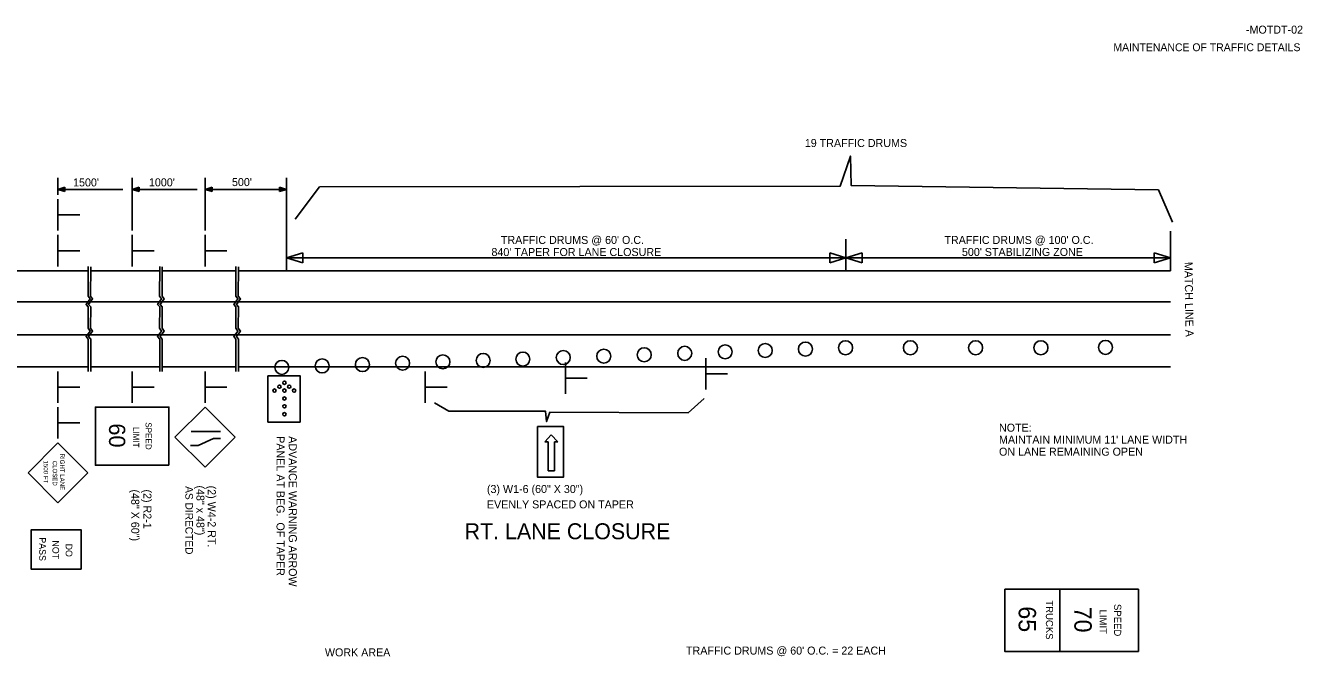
# Model space of a CAD drawing. Extents: x 37171 to 39457, y -18939 to -17445.
# Drawn here: x 38020 to 39456, y -18154 to -17445 of the extents above; entities that cross this region are included whole.
import ezdxf

# ---------------------------------------------------------------- set-up
doc = ezdxf.new("R2010")
doc.units = 0
for name, color, linetype in [('Default', 7, 'Continuous'), ('R_Const Phase 4', 7, 'Continuous'), ('R_Grid Annot', 7, 'Continuous'), ('R_Proposed Road Annot', 7, 'Continuous')]:
    doc.layers.add(name, color=color, linetype=linetype)

msp = doc.modelspace()

# ---------------------------------------------------------------- linework, layer by layer
at = {"layer": 'Default'}
for p, q in [((38221.4, -17873.7), (38187.6, -17907.5)), ((38221.4, -17873.7), (38255.1, -17907.5)), ((38205.7, -17901), (38238.9, -17901)), ((38603.6, -17912.6), (38610.8, -17904.7)), ((38610.8, -17904.7), (38618.1, -17912.6)), ((38022.3, -17947.7), (38055.9, -17914)), ((38089.6, -17947.6), (38055.9, -17914)), ((38187.6, -17907.5), (38221.4, -17941.2)), ((38205, -17916.7), (38213.6, -17916.7)), ((38213.6, -17916.7), (38230.8, -17908.8)), ((38255.1, -17907.5), (38221.4, -17941.2)), ((38230.8, -17908.8), (38238.9, -17908.8)), ((38607.2, -17912.6), (38603.6, -17912.6)), ((38607.2, -17945.3), (38607.2, -17912.6)), ((38614.5, -17945.3), (38614.5, -17912.6)), ((38614.5, -17912.6), (38618.1, -17912.6)), ((38056, -17981.4), (38022.3, -17947.7)), ((38056, -17981.4), (38089.6, -17947.6)), ((38607.2, -17945.3), (38614.5, -17945.3))]:
    msp.add_line(p, q, dxfattribs=at)
for points in [[(38292.1, -17838.5), (38292.1, -17890.6), (38328.2, -17890.6), (38328.2, -17838.5)], [(38180.7, -17939.1), (38098.2, -17939.1), (38098.2, -17873.7), (38180.7, -17873.7)], [(38595.3, -17895.4), (38595.3, -17952.6), (38624.5, -17952.6), (38624.5, -17895.4)], [(38081.9, -18056), (38025.9, -18056), (38025.9, -18011.6), (38081.9, -18011.6)], [(39182.7, -18148.6), (39121, -18148.6), (39121, -18078.6), (39182.7, -18078.6)], [(39271, -18148.6), (39182.7, -18148.6), (39182.7, -18078.6), (39271, -18078.6)]]:
    msp.add_lwpolyline(points, close=True, dxfattribs=at)
for centre, radius in [((38760.8, -17813.2), 7.88), ((38806.3, -17811.5), 7.88), ((38851.4, -17810), 7.88), ((38896.6, -17808.4), 7.88), ((38941.7, -17806.9), 7.88), ((39014.6, -17806.9), 7.88), ((39088, -17806.9), 7.88), ((39161.4, -17806.9), 7.88), ((39234, -17806.5), 7.88), ((38353.1, -17827.4), 7.88), ((38398.4, -17825.9), 7.88), ((38443.6, -17824.3), 7.88), ((38488.9, -17822.8), 7.88), ((38534.2, -17821.2), 7.88), ((38578.8, -17819.7), 7.88), ((38624.3, -17818), 7.88), ((38669.8, -17816.4), 7.88), ((38715.3, -17814.8), 7.88), ((38307.8, -17829), 7.88), ((38305.1, -17850.7), 1.84), ((38310.6, -17846.3), 1.84), ((38316.1, -17850.7), 1.84), ((38299.5, -17855.1), 1.84), ((38310.6, -17855.1), 1.84), ((38310.6, -17864), 1.84), ((38321.6, -17855.1), 1.84), ((38310.6, -17872.8), 1.84), ((38310.6, -17881.7), 1.84)]:
    msp.add_circle(centre, radius, dxfattribs=at)
at = {"layer": 'R_Const Phase 4'}
for p, q in [((38055.9, -17675.1), (38055.9, -17639.8)), ((38056.4, -17657.5), (38080.5, -17657.5)), ((38055.9, -17715.4), (38055.9, -17680.1)), ((38139.5, -17715.4), (38139.5, -17680.1)), ((38221.4, -17715.4), (38221.4, -17680.1)), ((38056.4, -17697.8), (38080.5, -17697.8)), ((38140, -17697.8), (38164, -17697.8)), ((38221.9, -17697.8), (38246, -17697.8)), ((38002.2, -17720.4), (38090, -17720.4)), ((38092.8, -17720.4), (38170.4, -17720.4)), ((38173.2, -17720.4), (38256.2, -17720.4)), ((38259, -17720.4), (38313, -17720.4)), ((38313, -17720.4), (39307.2, -17720.4)), ((37171.8, -17755.3), (39307.2, -17755.3)), ((37171.8, -17792.5), (39307.2, -17792.5)), ((38784.5, -17853.7), (38784.5, -17818.5)), ((38002.4, -17828.5), (38090.2, -17828.5)), ((38055.9, -17868.7), (38055.9, -17833.5)), ((38093, -17828.5), (38170.7, -17828.5)), ((38139.5, -17868.7), (38139.5, -17833.5)), ((38173.5, -17828.5), (38256.4, -17828.5)), ((38221.4, -17868.7), (38221.4, -17833.5)), ((38259.2, -17828.5), (38313, -17828.5)), ((38313, -17828.5), (39307.2, -17828.5)), ((38468.9, -17868.7), (38468.9, -17833.5)), ((38626.7, -17858.7), (38626.7, -17823.5)), ((38627.2, -17841.2), (38651.3, -17841.2)), ((38785, -17836.2), (38809.1, -17836.2)), ((38056.4, -17851.2), (38080.5, -17851.2)), ((38140, -17851.2), (38164, -17851.2)), ((38221.9, -17851.2), (38246, -17851.2)), ((38469.5, -17851.2), (38493.5, -17851.2)), ((38055.9, -17909), (38055.9, -17873.7)), ((38056.4, -17891.4), (38080.5, -17891.4))]:
    msp.add_line(p, q, dxfattribs=at)
for points in [[(38322.6, -17662.4), (38350.2, -17625.8), (38935.8, -17625.1), (38947.1, -17591.3), (38948.1, -17624.6), (39293.5, -17629.3), (39309.4, -17665.7)], [(38090, -17715.6), (38089.8, -17748.8), (38092.1, -17752.1), (38087.6, -17758.2), (38090, -17761)], [(38092.8, -17715.8), (38092.6, -17748.8), (38094.9, -17752.1), (38090.4, -17758.2), (38092.8, -17761)], [(38170.4, -17715.6), (38170.2, -17748.8), (38172.5, -17752.1), (38168.1, -17758.2), (38170.4, -17761)], [(38173.2, -17715.8), (38173, -17748.8), (38175.3, -17752.1), (38170.9, -17758.2), (38173.2, -17761)], [(38256.2, -17715.6), (38256, -17748.8), (38258.3, -17752.1), (38253.8, -17758.2), (38256.2, -17761)], [(38259, -17715.8), (38258.8, -17748.8), (38261.1, -17752.1), (38256.6, -17758.2), (38259, -17761)], [(38090, -17761), (38089.8, -17785)], [(38092.8, -17761), (38092.6, -17784.9)], [(38170.4, -17761), (38170.2, -17785)], [(38173.2, -17761), (38173, -17784.9)], [(38256.2, -17761), (38256, -17785)], [(38259, -17761), (38258.8, -17784.9)], [(38089.8, -17785), (38092.1, -17788.4), (38087.6, -17794.4), (38090, -17797.2), (38090, -17833.6)], [(38092.6, -17784.9), (38094.9, -17788.3), (38090.4, -17794.3), (38092.8, -17797.1), (38092.8, -17833.6)], [(38170.2, -17785), (38172.5, -17788.4), (38168.1, -17794.4), (38170.4, -17797.2), (38170.4, -17833.6)], [(38173, -17784.9), (38175.3, -17788.3), (38170.9, -17794.3), (38173.2, -17797.1), (38173.2, -17833.6)], [(38256, -17785), (38258.3, -17788.4), (38253.8, -17794.4), (38256.2, -17797.2), (38256.2, -17833.6)], [(38258.8, -17784.9), (38261.1, -17788.3), (38256.6, -17794.3), (38259, -17797.1), (38259, -17833.6)], [(38479.5, -17868.9), (38495.7, -17878.4), (38604.4, -17878.4), (38605.4, -17889.9), (38609.2, -17879.4), (38764.6, -17880.3), (38782.7, -17864.1)]]:
    msp.add_lwpolyline(points, dxfattribs=at)
at = {"layer": 'R_Proposed Road Annot'}
for p, q in [((38055.9, -17615.8), (38055.9, -17634.8)), ((38139.5, -17615.8), (38139.5, -17675.1)), ((38221.4, -17615.8), (38221.4, -17675.1)), ((38313, -17615.8), (38313, -17675.1)), ((38063.8, -17626.4), (38055.9, -17628.8)), ((38055.9, -17628.8), (38129, -17628.8)), ((38063.8, -17631.1), (38055.9, -17628.8)), ((38063.8, -17626.8), (38057.2, -17628.8)), ((38063.8, -17630.7), (38057.2, -17628.8)), ((38063.8, -17627.2), (38058.6, -17628.8)), ((38063.8, -17630.3), (38058.6, -17628.8)), ((38063.8, -17627.6), (38059.9, -17628.8)), ((38063.8, -17629.9), (38059.9, -17628.8)), ((38063.8, -17628), (38061.2, -17628.8)), ((38063.8, -17629.5), (38061.2, -17628.8)), ((38063.8, -17628.4), (38062.5, -17628.8)), ((38063.8, -17629.1), (38062.5, -17628.8)), ((38063.8, -17631.1), (38063.8, -17626.4)), ((38147.3, -17626.4), (38139.5, -17628.8)), ((38139.5, -17628.8), (38212.5, -17628.8)), ((38147.3, -17631.1), (38139.5, -17628.8)), ((38147.3, -17626.8), (38140.8, -17628.8)), ((38147.3, -17630.7), (38140.8, -17628.8)), ((38147.3, -17627.2), (38142.1, -17628.8)), ((38147.3, -17630.3), (38142.1, -17628.8)), ((38147.3, -17627.6), (38143.4, -17628.8)), ((38147.3, -17629.9), (38143.4, -17628.8)), ((38147.3, -17628), (38144.8, -17628.8)), ((38147.3, -17629.5), (38144.8, -17628.8)), ((38147.3, -17628.4), (38146.1, -17628.8)), ((38147.3, -17629.1), (38146.1, -17628.8)), ((38147.3, -17631.1), (38147.3, -17626.4)), ((38229.3, -17626.4), (38221.4, -17628.8)), ((38221.4, -17628.8), (38313, -17628.8)), ((38229.3, -17631.1), (38221.4, -17628.8)), ((38229.3, -17626.8), (38222.7, -17628.8)), ((38229.3, -17630.7), (38222.7, -17628.8)), ((38229.3, -17627.2), (38224, -17628.8)), ((38229.3, -17630.3), (38224, -17628.8)), ((38229.3, -17627.6), (38225.4, -17628.8)), ((38229.3, -17629.9), (38225.4, -17628.8)), ((38229.3, -17628), (38226.7, -17628.8)), ((38229.3, -17629.5), (38226.7, -17628.8)), ((38229.3, -17628.4), (38228, -17628.8)), ((38229.3, -17629.1), (38228, -17628.8)), ((38229.3, -17631.1), (38229.3, -17626.4)), ((38305.2, -17626.4), (38313, -17628.8)), ((38305.2, -17626.4), (38305.2, -17631.1)), ((38305.2, -17626.8), (38311.7, -17628.8)), ((38305.2, -17627.2), (38310.4, -17628.8)), ((38305.2, -17627.6), (38309.1, -17628.8)), ((38305.2, -17628), (38307.7, -17628.8)), ((38305.2, -17628.4), (38306.4, -17628.8)), ((38305.2, -17631.1), (38313, -17628.8)), ((38305.2, -17629.5), (38307.7, -17628.8)), ((38305.2, -17630.3), (38310.4, -17628.8)), ((38305.2, -17630.7), (38311.7, -17628.8)), ((38305.2, -17629.9), (38309.1, -17628.8)), ((38305.2, -17629.1), (38306.4, -17628.8)), ((38313, -17675.1), (38313, -17720.4)), ((39307.2, -17675.7), (39307.2, -17720.4)), ((38942.1, -17684.7), (38942.1, -17720.4)), ((38313, -17705.8), (38331.3, -17700.3)), ((38942.1, -17705.8), (38313, -17705.8)), ((38331.3, -17711.3), (38313, -17705.8)), ((38331.3, -17700.3), (38331.3, -17711.3)), ((38923.9, -17711.3), (38923.9, -17700.3)), ((38923.9, -17700.3), (38942.1, -17705.8)), ((38942.1, -17705.8), (38923.9, -17711.3)), ((38942.1, -17705.8), (38960.4, -17700.3)), ((39307.2, -17705.8), (38942.1, -17705.8)), ((38960.4, -17711.3), (38942.1, -17705.8)), ((38960.4, -17700.3), (38960.4, -17711.3)), ((39288.9, -17711.3), (39288.9, -17700.3)), ((39288.9, -17700.3), (39307.2, -17705.8)), ((39307.2, -17705.8), (39288.9, -17711.3))]:
    msp.add_line(p, q, dxfattribs=at)

# ---------------------------------------------------------------- texts
at = {"layer": 'Default'}
for s, height, rotation, p in [('SPEED', 6.81, 270, (38154.5, -17890.7)), ('60', 18.25, 270, (38113.4, -17892)), ('LIMIT', 6.81, 270, (38140.5, -17896)), ('1500 FT', 4.99, 270.0006, (38039.9, -17933.7)), ('CLOSED', 4.96, 270.1003, (38050.1, -17934)), ('RIGHT LANE', 4.96, 270.1004, (38058.4, -17926)), ('PASS', 7.45, 270, (38034.9, -18020.1)), ('NOT', 7.45, 270, (38049.8, -18023.6)), ('DO', 7.45, 270, (38064.7, -18027.2)), ('TRUCKS', 8.02, 270, (39167, -18091)), ('65', 19.54, 270, (39136.4, -18097.7)), ('70', 19.54, 270, (39199, -18098.1)), ('LIMIT', 8.02, 270, (39227.3, -18101.3)), ('SPEED', 8.02, 270, (39243.7, -18095.1))]:
    msp.add_text(s, height=height, rotation=rotation, dxfattribs=at).set_placement(p)
at = {"layer": 'R_Grid Annot'}
for s, height, p in [('-MOTDT-02', 9, (39392, -17453.7)), ('MAINTENANCE OF TRAFFIC DETAILS', 8.793, (39242.9, -17473.4))]:
    msp.add_text(s, height=height, dxfattribs=at).set_placement(p)
at = {"layer": 'R_Proposed Road Annot'}
for s, height, p in [('19 TRAFFIC DRUMS', 9, (38895.9, -17581.2)), ("1500'", 9, (38073, -17625.5)), ("1000'", 9, (38158.3, -17625.4)), ("500'", 9, (38251.7, -17625.1)), ("TRAFFIC DRUMS @ 60' O.C.", 9, (38554.1, -17690.2)), ("TRAFFIC DRUMS @ 100' O.C.", 9, (39052.9, -17690.2)), ("840' TAPER FOR LANE CLOSURE", 9, (38543.5, -17703.8)), ("500' STABILIZING ZONE", 9, (39072.6, -17703.7)), ('NOTE:', 9, (39114.3, -17901.3)), ("MAINTAIN MINIMUM 11' LANE WIDTH", 9, (39114.3, -17914.8)), ('ON LANE REMAINING OPEN', 9, (39114.3, -17928.3)), ('RT. LANE CLOSURE', 18, (38513.3, -18022.3)), ('WORK AREA', 9, (38356.2, -18154)), ("TRAFFIC DRUMS @ 60' O.C. = 22 EACH", 9, (38762.3, -18152))]:
    msp.add_text(s, height=height, dxfattribs=at).set_placement(p)
for s, height, rotation, p in [('MATCH LINE A', 9, 270.8059, (39322.9, -17710.5)), ('ADVANCE WARNING ARROW', 9, 270, (38315.6, -17906.4)), ('PANEL AT BEG.  OF TAPER', 9, 270, (38301.8, -17906.4)), ('AS DIRECTED ', 8.54, 270, (38199.3, -17962.6)), ('(48" x 48")', 9, 270, (38211.7, -17961.8)), ('(2) W4-2 RT.', 9, 270, (38224.5, -17962)), ('(3) W1-6 (60" X 30")', 9, 0.0075, (38538.4, -17970.3)), ('(48" X 60")', 9, 270, (38138.4, -17966.3)), ('(2) R2-1', 9, 270, (38152.1, -17966.3)), ('EVENLY SPACED ON TAPER', 9, 0.0075, (38538.4, -17987.6))]:
    msp.add_text(s, height=height, rotation=rotation, dxfattribs=at).set_placement(p)

doc.saveas('drawing.dxf')
